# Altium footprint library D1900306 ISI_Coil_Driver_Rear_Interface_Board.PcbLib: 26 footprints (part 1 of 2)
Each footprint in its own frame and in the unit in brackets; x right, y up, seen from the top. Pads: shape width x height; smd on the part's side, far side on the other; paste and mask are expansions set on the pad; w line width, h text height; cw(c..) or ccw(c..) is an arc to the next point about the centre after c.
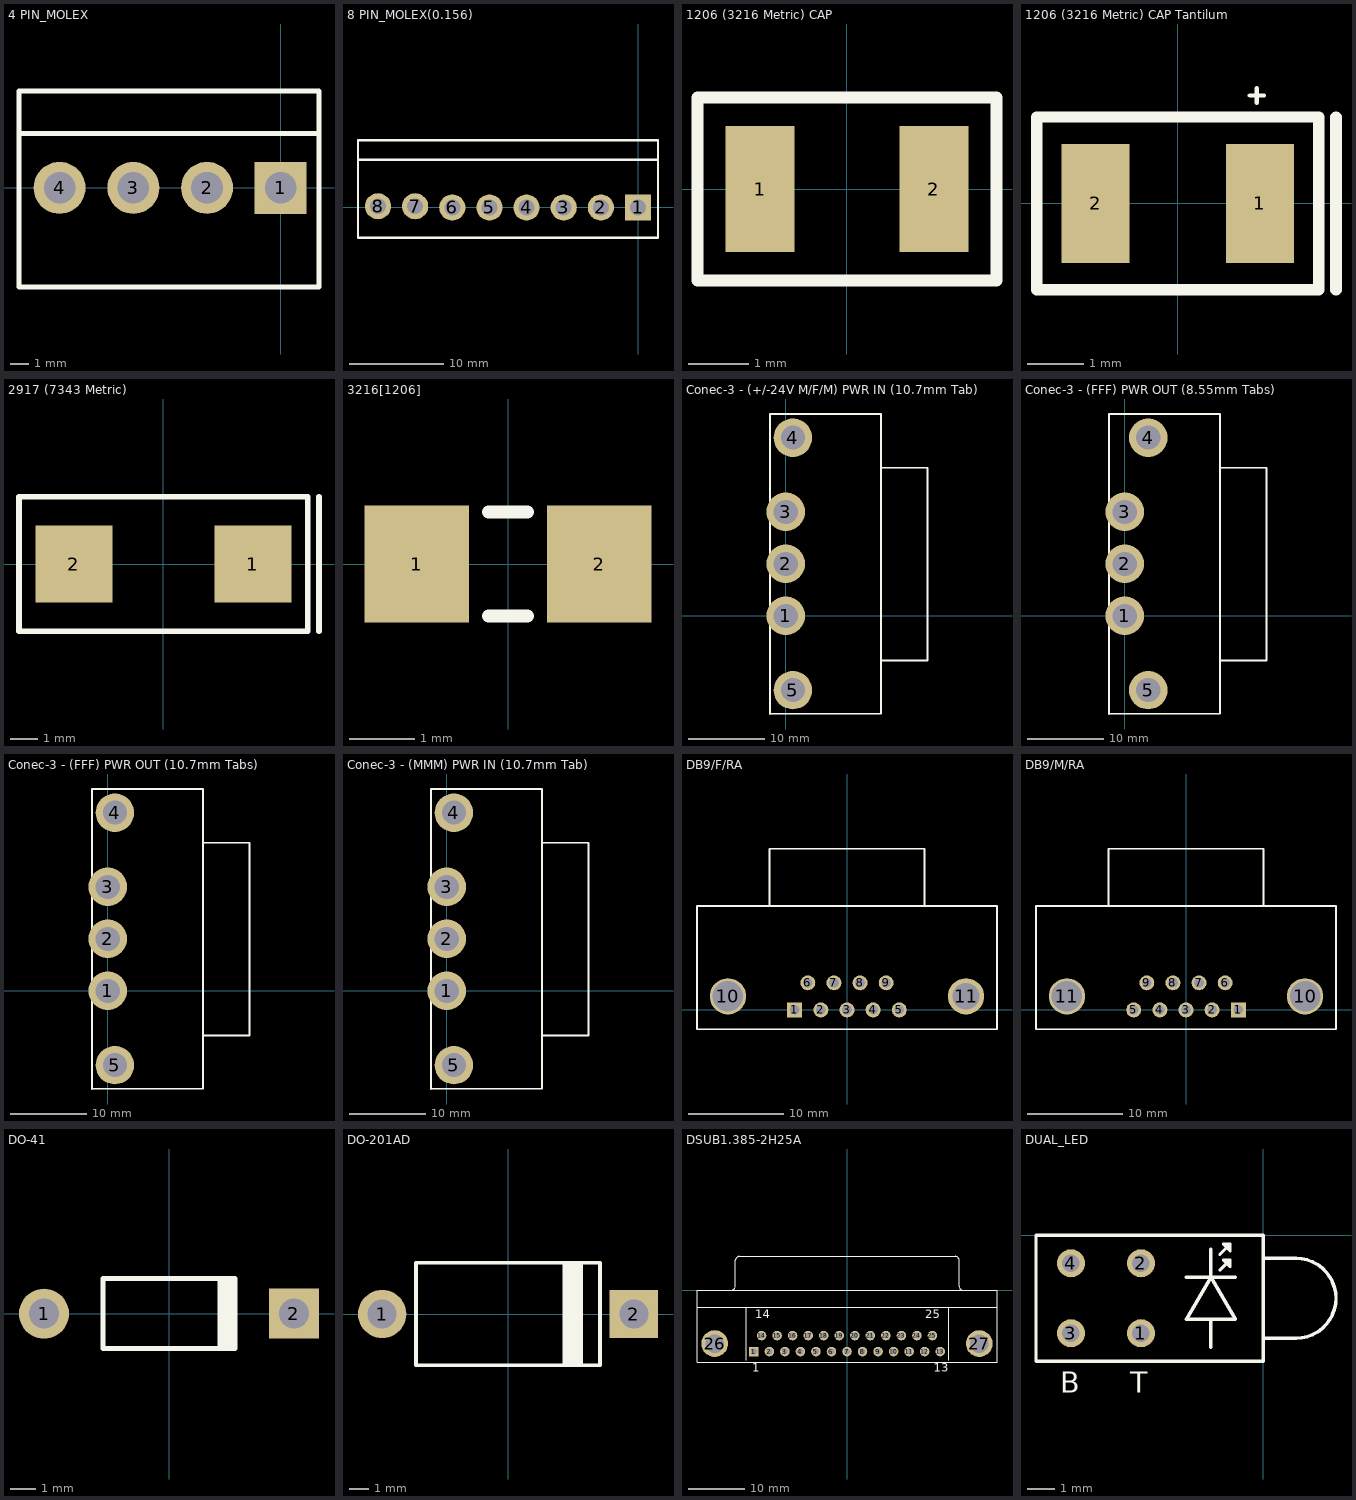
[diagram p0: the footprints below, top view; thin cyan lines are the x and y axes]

## 4 PIN_MOLEX [mil]
pads (4):
  rect 110x110 hole 67: 1(0,0)
  round 110 hole 67: 2(-156,0) 3(-312,0) 4(-468,0)
Top Overlay:
  lines w10: -554,115 80,115 ; -554,-210 81,-210 81,205 -554,205 -554,-210
3D body "MOLEX 4pin 3.96mm (026604040).stp": height 580.5, standoff -139.5, extent -543.99,-198.75 74,195.25

## 8 PIN_MOLEX(0.156) [mil]
pads (8):
  rect 110x110 hole 67: 1(0,0)
  round 110 hole 67: 2(-156,0) 3(-312,0) 4(-468,0) 5(-624,0) 6(-780,0) 7(-936,5) 8(-1092,5)
Top Overlay:
  lines w10: -1176,200 84,200 ; -1176,-127.5 -1176,282.5 84,282.5 84,-127.5 -1176,-127.5
3D body "MOLEX 8pin 3.96mm (0026604080).stp": height 580.5, standoff -139.5, extent -1167,-121.25 75,272.75

## 1206 (3216 Metric) CAP [mm] "Chip Capacitor; Body 3.2 x 1.6 mm (LxW typ)"
height 1.5
pads (2):
  rect 1.15x2.1 smd: 1(-1.45,0) 2(1.45,0)
Top Overlay:
  lines w0.2: -2.489,-1.524 -2.489,1.524 2.489,1.524 2.489,-1.524 -2.489,-1.524
3D body "1206 (3216 Metric) CAP.step": height 1.11, standoff 0.01, extent -1.8,-0.935 1.8,0.965

## 1206 (3216 Metric) CAP Tantilum [mm] "Chip Capacitor; Body 3.2 x 1.6 mm (LxW typ)"
height 1.5
pads (2):
  rect 1.2x2.1 smd: 1(1.45,0) 2(-1.45,0)
Top Overlay:
  lines w0.076: 1.27,1.905 1.524,1.905 ; 1.397,1.778 1.397,2.032
  lines w0.2: -2.489,-1.524 -2.489,1.524 2.489,1.524 2.489,-1.524 -2.489,-1.524
  lines w0.203: 2.794,-1.524 2.794,1.524
3D body "TAJA.step": height 1.85, standoff 0, extent -1.702,-0.902 1.702,0.902

## 2917 (7343 Metric) [mm]
height 10.44
pads (2):
  rect 2.77x2.77 smd: 1(3.22,0) 2(-3.22,0)
Top Overlay:
  lines w0.2: 5.6,-2.413 5.6,2.413 ; -5.2,-2.413 5.2,-2.413 5.2,2.413 -5.2,2.413 -5.2,-2.413
3D body "Tantilum Case X (T521X106M075ATE050).step": height 4.31, standoff 0.01, extent -3.8,-2.286 3.8,2.314

## 3216[1206] [mm] "Chip Resistor; Body 3.2 x 1.6 mm (LxW typ)"
height 2.54
pads (2):
  rect 1.6x1.8 smd: 1(-1.4,0) 2(1.4,0)
Top Overlay:
  lines w0.2: -0.3,-0.8 0.3,-0.8 ; -0.3,0.8 0.3,0.8
3D body "RES 1206 (3216).step": height 0.55, standoff 0, extent -1.6,-0.8 1.6,0.8

## Conec-3 - (+/-24V M/F/M) PWR IN (10.7mm Tab) [mil] "303W3CPXX56K40X"
pads (5):
  round 200 hole 125: 1(0,0) 2(0,270) 3(0,540) 4(37.4,925) 5(37.4,-386)
Top Overlay:
  lines w10: 494.4,-232 736.4,-232 736.4,769 494.4,767 ; -82.6,1048 -80.6,-510 494.4,-508 494.4,1048 -82.6,1048
3D body "24V PWR Connector (303W3CPXX75G40X).stp": height 543.81, standoff -137.29, extent -86.92,-502.05 747.72,1042.05

## Conec-3 - (FFF) PWR OUT (8.55mm Tabs) [mil] "3003W3SXX56N40X"
pads (5):
  round 200 hole 125: 1(0,0) 2(0,270) 3(0,540) 4(122.05,925) 5(122.05,-386)
Top Overlay:
  lines w10: 494.4,-232 736.4,-232 736.4,769 494.4,767 ; -82.6,1048 494.4,1048 494.4,-508 -80.6,-510 -82.6,1048
3D body "Conec-3 PWR OUT 90deg (3F3SSC28S56K40X).STEP": height 497.55, standoff -182.57, extent -56.57,-500.47 725.91,1040.48

## Conec-3 - (FFF) PWR OUT (10.7mm Tabs) [mil] "3003W3SXX56K40X"
pads (5):
  round 200 hole 125: 1(0,0) 2(0,270) 3(0,540) 4(37.4,925) 5(37.4,-386)
Top Overlay:
  lines w10: 494.4,-232 736.4,-232 736.4,769 494.4,767 ; -82.6,1048 -80.6,-510 494.4,-508 494.4,1048 -82.6,1048
3D body "3003W3SXX56K40K.stp": height 498.53, standoff -182.57, extent -78.73,-502.05 748.04,1042.05

## Conec-3 - (MMM) PWR IN (10.7mm Tab) [mil]
pads (5):
  round 200 hole 125: 1(0,0) 2(0,270) 3(0,540) 4(37.4,925) 5(37.4,-386)
Top Overlay:
  lines w10: 494.4,-232 736.4,-232 736.4,769 494.4,767 ; -82.6,1048 494.4,1048 494.4,-508 -80.6,-510 -82.6,1048
3D body "Conec-3 PWR IN (3F3SPC05S56K40X).stp": height 498.53, standoff -182.57, extent -75.11,-502.05 735.91,1042.05

## DB9/F/RA [mil] "Amphenol part# 617-C009S-AJ120"
pads (11):
  rect 62x62 hole 40: 1(-216,0)
  round 62 hole 40: 2(-108,0) 3(0,0) 4(108,0) 5(216,0) 6(-162,112) 7(-54,112) 8(54,112) 9(162,112)
  round 150 hole 126: 10(-492,56)
  round 150 hole 110: 11(492,56)
Top Overlay:
  lines w8: -321,430 -321,666 321,666 321,430 ; -620,-80 620,-80 620,430 -620,430 -620,-80
3D body "D9F 90deg (A32117-ND).stp": height 494.5, standoff -127.9, extent -610,-70 610,673.9

## DB9/M/RA [mil] "Amphenol Part# 617-C009P-AJ120"
pads (11):
  rect 62x62 hole 40: 1(216,0)
  round 62 hole 40: 2(108,0) 3(0,0) 4(-108,0) 5(-216,0) 6(162,112) 7(54,112) 8(-54,112) 9(-162,112)
  round 150 hole 126: 10(492,56) 11(-492,56)
Top Overlay:
  lines w8: -321,430 -321,666 321,666 321,430 ; -620,-80 620,-80 620,430 -620,430 -620,-80
3D body "D9M 90deg (A32091-ND).stp": height 494.5, standoff -127.9, extent -611,-70 611,662.4

## DO-41 [mm] "Diode, Axial; Body 5.2 x 2.7 mm (LxDia. max), Lead Dia. 0.86 mm (max)"
height 2.8
pads (2):
  round 2 hole 1.2: 1(-5,0)
  rect 2x2 hole 1.2: 2(5,0)
Top Overlay:
  rectangle: 1.95,-1.423 2.75,1.377
  lines w0.2: 2.65,-1.4 -2.65,-1.4 -2.65,1.4 2.65,1.4
3D body "DO-41 10mm.step": height 2.86, standoff -2.5, extent -5.399,-1.362 5.461,1.362

## DO-201AD [mm] "Diode Standard 400V 3A Through Hole DO-201AD"
height 2.8
pads (2):
  round 2.5 hole 1.5: 1(-6.5,0)
  rect 2.5x2.5 hole 1.5: 2(6.5,0)
Top Overlay:
  lines w0.2: 2.925,-2.65 2.925,2.65 ; 3.1,-2.65 3.1,2.65 ; 3.275,-2.65 3.275,2.65 ; 3.45,-2.65 3.45,2.65 ; 3.625,-2.65 3.625,2.65 ; 3.775,-2.65 3.775,2.65 ; -4.75,-2.65 -4.75,2.65 4.75,2.65 4.75,-2.65 -4.75,-2.65
3D body "1N5404.step": height 5.51, standoff -2.85, extent -6.95,-2.575 6.95,2.447

## DSUB1.385-2H25A [mm] "Connector; D Subminiature; 25 Position; Right Angle; Pitch 1.385 mm"
height 12.93
pads (27):
  rect 1.69x1.69 hole 1.09: 1(-16.566,-10.92)
  round 1.69 hole 1.09: 2(-13.805,-10.92) 3(-11.044,-10.92) 4(-8.283,-10.92) 5(-5.522,-10.92) 6(-2.761,-10.92) 7(0,-10.92) 8(2.761,-10.92) 9(5.522,-10.92) 10(8.283,-10.92) 11(11.044,-10.92) 12(13.805,-10.92) 13(16.566,-10.92) 14(-15.185,-8.08) 15(-12.425,-8.08) 16(-9.663,-8.08) 17(-6.903,-8.08) 18(-4.142,-8.08) 19(-1.38,-8.08) 20(1.38,-8.08) 21(4.142,-8.08) 22(6.903,-8.08) 23(9.663,-8.08) 24(12.425,-8.08) 25(15.185,-8.08)
  round 4.76 hole 3.26: 26(-23.526,-9.5) 27(23.526,-9.5)
Top Overlay:
  lines w0.2: -26.67,-3 26.604,-3 ; -20.541,0.005 ccw(c-20.541,0.7) -19.846,0.7 -19.846,5.3 ; -19.841,5.305 cw(c-19.146,5.305) -19.146,6 19.254,6 cw(c19.254,5.305) 19.949,5.305 ; -17.946,-12.5 -17.946,-3 ; 18.054,-12.5 18.054,-3 ; 19.954,5.3 19.954,0.7 ccw(c20.649,0.7) 20.649,0.005 ; -26.67,-12.827 26.67,-12.827 26.67,0 -26.67,0 -26.67,-12.827
  text "1" at -16.816,-14.475 h1.5
  text "13" at 15.441,-14.475 h1.5
  text "14" at -16.31,-4.975 h1.5
  text "25" at 13.936,-4.975 h1.5
3D body "D25F 90deg (5788800-2).stp": height 12.56, standoff -3.16, extent -26.543,-12.7 26.543,6.248

## DUAL_LED [mil] "Stacked LED GREEN, Digi Key Part # 67-1321-ND"
pads (4):
  round 40 hole 25: 1(-175,-140) 2(-175,-40) 3(-275,-140) 4(-275,-40)
Top Overlay:
  lines w4: -62.5,-50 -47.5,-35 ; -62.5,-27.5 -47.5,-12.5 ; -47.5,-35 -47.5,-45 -57.5,-35 -47.5,-35 ; -47.5,-12.5 -57.5,-12.5 -47.5,-22.5 -47.5,-12.5
  lines w5: -110,-60 -40,-60 ; -75,-160 -75,-120 ; -75,-20 -75,-60 ; 0,-180 -135,-180 -325,-180 -325,0 0,0 0,-179.39 ; 3.23,-147.09 46.54,-147.09 ccw(c46.54,-90) 46.54,-32.91 3.23,-32.91 ; -75,-60 -110,-120 -40,-120 -75,-60
  text "T" at -190,-225 h29.53
  text "B" at -290,-225 h29.53
3D body "LED 2x1 Lumex SSF-LXH240GGD (1).step": height 380.42, standoff -124.7, extent -320,-175.04 104.02,-4.96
